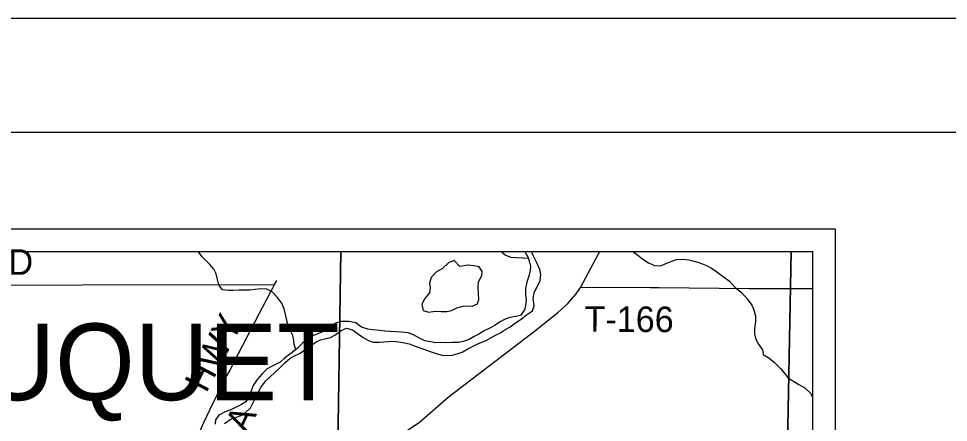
# Model space of a CAD drawing. Extents: x -784 to 1375, y -225 to 440.
# Drawn here: x 133.1 to 215.1, y 404.5 to 440 of the extents above; entities that cross this region are included whole.
import ezdxf

# ---------------------------------------------------------------- set-up
doc = ezdxf.new("R2010")
doc.units = 0
for name, color, linetype in [('GM_X_County_Road', 7, 'Continuous'), ('GM_X_County_Road_Text', 7, 'Continuous'), ('GM_X_Major_River', 7, 'Continuous'), ('GM_X_Minor_Lake', 7, 'Continuous'), ('GM_X_Minor_River', 7, 'Continuous'), ('GM_X_Section', 7, 'Continuous'), ('GM_X_State_Route', 7, 'Continuous'), ('GM_X_Township_Road', 7, 'Continuous'), ('GM_X_Township_Road_Text', 7, 'Continuous'), ('GM_X_Township_Text', 7, 'Continuous'), ('SH_Border', 7, 'Continuous'), ('SH_Cut_Line', 7, 'Continuous'), ('SH_Data', 7, 'Continuous'), ('SH_Text', 7, 'Continuous')]:
    doc.layers.add(name, color=color, linetype=linetype)

msp = doc.modelspace()

# ---------------------------------------------------------------- linework, layer by layer
at = {"layer": 'GM_X_County_Road'}
for points in [[(121.642, 416.536), (155.683, 416.584)], [(155.503, 416.254), (155.683, 416.584), (155.863, 416.943)], [(151.66, 408.91), (152.492, 410.521), (153.942, 413.279), (154.355, 414.08), (154.637, 414.623), (155.355, 415.984), (155.503, 416.254)], [(146.605, 397.971), (146.834, 398.493), (148.809, 403.029), (149.446, 404.455), (150.224, 406.13), (151.468, 408.539), (151.66, 408.91)]]:
    msp.add_lwpolyline(points, dxfattribs=at)
at = {"layer": 'GM_X_Major_River'}
for points in [[(156.177, 409.296), (156.649, 409.755), (157.028, 410.066), (157.422, 410.3), (157.936, 410.534), (158.452, 410.917), (158.922, 411.256), (159.331, 411.535), (159.724, 411.725), (160.222, 411.853), (160.599, 411.938), (160.992, 412.128), (161.538, 412.541), (162.006, 412.745), (162.545, 412.602), (163.066, 412.22), (163.497, 411.914), (163.96, 411.667), (164.378, 411.526), (164.934, 411.519), (165.31, 411.558), (166.167, 411.592), (166.631, 411.54), (167.141, 411.458), (167.53, 411.363), (168.248, 411.113), (168.756, 410.941), (169.384, 410.707), (169.907, 410.505), (170.446, 410.377), (170.881, 410.356), (171.317, 410.38), (171.769, 410.494), (172.222, 410.638), (172.706, 410.917), (173.13, 411.136), (173.659, 411.399), (174.279, 411.646), (174.748, 411.909), (175.141, 412.144), (175.534, 412.319), (175.974, 412.598), (176.428, 412.862), (176.899, 413.231), (177.414, 413.554), (177.884, 413.923), (178.415, 414.276), (178.556, 414.709), (178.475, 415.356), (178.557, 415.895), (178.819, 416.387), (179.082, 416.939), (179.149, 417.463), (179.065, 417.9), (178.832, 418.444), (178.466, 419.139), (178.328, 419.485)], [(177.729, 419.485), (177.793, 419.389), (178.043, 418.98), (178.158, 418.573), (178.228, 418.197), (178.208, 417.822), (178.096, 417.313), (177.923, 416.805), (177.781, 416.236), (177.789, 415.726), (177.857, 415.199), (177.804, 414.675), (177.71, 414.361), (177.343, 413.87), (176.801, 413.758), (176.424, 413.673), (176.016, 413.528), (175.502, 413.265), (175.123, 413.015), (174.714, 412.781), (174.155, 412.518), (173.686, 412.224), (173.262, 412.02), (172.823, 411.741), (172.31, 411.568), (171.903, 411.498), (171.362, 411.491), (170.701, 411.47), (170.311, 411.475), (169.875, 411.466), (169.44, 411.532), (168.931, 411.644), (168.453, 411.861), (167.917, 412.153), (167.453, 412.34), (166.869, 412.408), (166.343, 412.415), (165.893, 412.451), (165.383, 412.488), (164.948, 412.539), (164.348, 412.608), (163.898, 412.659), (163.33, 412.847), (162.839, 413.229), (162.225, 413.342), (161.579, 413.321), (161.066, 413.178), (160.687, 412.913), (160.202, 412.574), (159.793, 412.37), (159.159, 412.138), (158.69, 411.844), (158.159, 411.446), (157.641, 410.943), (157.094, 410.515), (156.563, 410.102), (156.183, 409.762)], [(156.183, 409.762), (155.593, 409.455), (155.033, 409.162), (154.561, 408.703), (154.15, 408.243), (153.782, 407.693), (153.61, 407.245), (153.439, 406.766), (153.132, 406.275), (152.753, 406.025), (152.299, 405.806), (151.83, 405.572), (151.317, 405.384), (150.773, 405.091), (150.482, 404.675), (150.431, 404.285)], [(151.258, 404.349), (151.759, 404.717), (152.136, 404.847), (152.634, 405.036), (153.058, 405.255), (153.545, 405.744), (153.853, 406.31), (154.116, 406.847), (154.455, 407.518), (154.883, 408.068), (155.279, 408.468), (155.705, 408.837), (156.177, 409.296)]]:
    msp.add_lwpolyline(points, dxfattribs=at)
at = {"layer": 'GM_X_Minor_Lake'}
for points in [[(172.02, 418.18), (171.52, 418.709), (170.992, 418.491), (170.489, 418.003), (169.96, 417.71), (169.472, 417.206), (169.345, 416.698), (169.385, 416.322), (169.319, 415.857), (168.891, 415.323), (168.644, 414.846), (168.787, 414.303), (169.266, 414.162), (169.823, 414.259), (170.333, 414.222), (170.859, 414.23), (171.265, 414.314), (171.749, 414.533), (172.307, 414.675), (172.683, 414.7), (173.088, 414.694), (173.556, 414.883), (173.667, 415.272), (173.659, 415.813), (173.636, 416.308), (173.643, 416.819), (173.951, 417.385)], [(173.951, 417.385), (173.985, 417.73), (173.706, 418.139), (173.241, 418.235), (172.731, 418.302), (172.02, 418.18)]]:
    msp.add_lwpolyline(points, dxfattribs=at)
at = {"layer": 'GM_X_Minor_River'}
msp.add_line((178.357, 419.413), (178.429, 419.485), dxfattribs=at)
for points in [[(157.561, 410.881), (157.406, 411.321), (157.366, 411.697), (157.281, 412.089), (157.047, 412.587), (156.872, 412.965), (156.744, 413.462), (156.674, 413.839), (156.517, 414.441), (156.313, 414.939), (155.9, 415.471), (155.5, 415.912), (154.993, 416.174), (154.453, 416.211), (153.956, 416.158), (153.46, 416.105), (153.069, 416.095), (152.543, 416.087), (152.003, 416.079), (151.612, 416.055), (151.087, 416.137), (150.763, 416.577), (150.649, 417.044), (150.52, 417.541), (150.315, 417.934), (149.976, 418.359), (149.324, 419.013), (148.932, 419.485)], [(178.071, 418.881), (177.546, 418.897), (176.991, 418.934), (176.526, 418.971), (176.003, 419.173), (175.616, 419.485)], [(187.248, 419.485), (187.689, 419.162), (188.15, 418.826), (188.642, 418.503), (189.179, 418.256), (189.689, 418.234), (190.263, 418.466), (190.686, 418.655), (191.109, 418.8), (191.68, 418.822), (192.19, 418.77), (192.654, 418.643), (193.163, 418.486), (193.76, 418.253), (194.193, 418.022), (194.654, 417.7), (195.204, 417.287), (195.769, 416.874), (196.288, 416.341), (196.838, 415.883), (197.326, 415.336), (197.739, 414.76), (197.928, 414.352), (198.071, 413.81), (198.064, 413.314), (197.981, 412.715), (197.99, 412.235), (198.075, 411.858), (198.308, 411.36), (198.677, 410.844), (198.731, 410.423), (199.238, 410.146), (199.743, 409.719), (200.277, 409.186), (200.587, 408.806), (200.927, 408.411), (201.433, 408.044), (201.895, 407.782), (202.417, 407.505), (202.936, 407.002), (203.088, 406.677)]]:
    msp.add_lwpolyline(points, dxfattribs=at)
at = {"layer": 'GM_X_Section'}
for points in [[(161.508, 419.485), (161.159, 396.705), (133.637, 396.836)], [(201.225, 419.485), (200.783, 396.352), (161.159, 396.705), (161.508, 419.485)], [(203.088, 396.355), (200.783, 396.352), (201.225, 419.485)]]:
    msp.add_lwpolyline(points, dxfattribs=at)
at = {"layer": 'GM_X_State_Route'}
msp.add_lwpolyline([(166.701, 403.31), (168.426, 404.455), (170.986, 406.675), (178.697, 412.562), (180.635, 414.124), (181.532, 414.933), (182.258, 415.778), (182.635, 416.335), (184.243, 419.294), (184.349, 419.485)], dxfattribs=at)
at = {"layer": 'GM_X_Township_Road'}
msp.add_lwpolyline([(182.635, 416.335), (184, 416.354), (188.769, 416.322), (188.815, 416.321), (189.563, 416.315), (197.511, 416.254), (197.691, 416.251), (198.306, 416.25), (203.075, 416.241), (203.088, 416.241)], dxfattribs=at)
at = {"layer": 'SH_Border'}
msp.add_lwpolyline([(30, 430), (670, 430), (670, 10), (30, 10)], close=True, dxfattribs=at)
at = {"layer": 'SH_Cut_Line'}
msp.add_lwpolyline([(0, 0), (680, 0), (680, 440), (0, 440)], close=True, dxfattribs=at)
at = {"layer": 'SH_Data'}
for p, q in [((65.088, 421.485), (205.088, 421.485)), ((205.088, 421.485), (205.088, 281.485))]:
    msp.add_line(p, q, dxfattribs=at)
at = {"layer": 'SH_Text'}
msp.add_lwpolyline([(67.088, 419.485), (203.088, 419.485), (203.088, 283.485), (67.088, 283.485)], close=True, dxfattribs=at)

# ---------------------------------------------------------------- texts
at = {"layer": 'GM_X_County_Road_Text'}
for s, rotation, p in [('RD', 0.00001, (130.046, 417.447)), ('HWY', 62.40181, (149.653, 406.974)), ('A', 64.68293, (153.281, 403.39))]:
    msp.add_text(s, height=2.25, rotation=rotation, dxfattribs=at).set_placement(p)
at = {"layer": 'GM_X_Township_Road_Text'}
msp.add_text('T-166', height=2.25, rotation=359.71999, dxfattribs=at).set_placement((182.992, 412.434))
at = {"layer": 'GM_X_Township_Text'}
msp.add_text('DUCHOUQUET', height=6.75, rotation=0.00001, dxfattribs=at).set_placement((96.718, 406.407))

doc.saveas('drawing.dxf')
